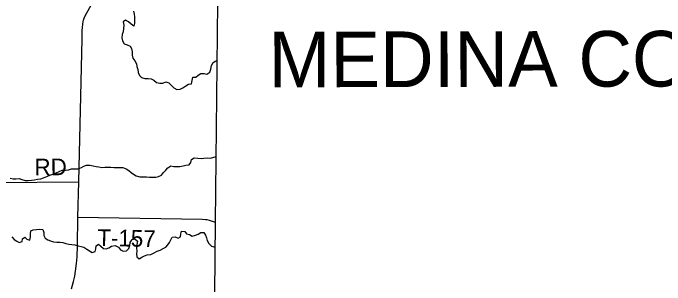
# Model space of a CAD drawing. Extents: x 1857828 to 2277390, y 930619 to 1324581.
# Drawn here: x 2082450 to 2094171, y 1160303 to 1165195 of the extents above; entities that cross this region are included whole.
import ezdxf

# ---------------------------------------------------------------- set-up
doc = ezdxf.new("R2010")
doc.units = 0
for name, color, linetype in [('GM_X_Adjacent_County', 7, 'Continuous'), ('GM_X_Adjacent_County_Text', 7, 'Continuous'), ('GM_X_County', 7, 'Continuous'), ('GM_X_County_Road', 7, 'Continuous'), ('GM_X_Minor_River', 7, 'Continuous'), ('GM_X_Township', 7, 'Continuous'), ('GM_X_Township_Road', 7, 'Continuous'), ('GM_X_Township_Road_Text', 7, 'Continuous')]:
    doc.layers.add(name, color=color, linetype=linetype)

msp = doc.modelspace()

# ---------------------------------------------------------------- linework, layer by layer
at = {"layer": 'GM_X_Adjacent_County'}
msp.add_lwpolyline([(2117908, 1193445), (2113523, 1193411), (2113466, 1188070), (2113428, 1184374), (2113417, 1179845), (2113408, 1176168), (2113399, 1174227), (2113372, 1168723), (2113358, 1166008), (2106159, 1165987), (2105360, 1165986), (2099554, 1165974), (2091388, 1165958), (2088816, 1165953), (2086130, 1165948), (2086087, 1161432), (2086019, 1154363)], dxfattribs=at)
at = {"layer": 'GM_X_County'}
msp.add_lwpolyline([(2117908, 1193445), (2113523, 1193411), (2113466, 1188070), (2113428, 1184374), (2113417, 1179845), (2113408, 1176168), (2113399, 1174227), (2113372, 1168723), (2113358, 1166008), (2106159, 1165987), (2105360, 1165986), (2099554, 1165974), (2091388, 1165958), (2088816, 1165953), (2086130, 1165948), (2086087, 1161432), (2086019, 1154363)], dxfattribs=at)
at = {"layer": 'GM_X_County_Road'}
msp.add_lwpolyline([(2083504, 1160231), (2083539, 1160367), (2083560, 1160459), (2083574, 1160552), (2083591, 1160692), (2083602, 1160810), (2083612, 1161005), (2083617, 1161525), (2083632, 1162159), (2083692, 1164734), (2083695, 1164883), (2083697, 1164933), (2083704, 1164997), (2083712, 1165043), (2083720, 1165069), (2083732, 1165101), (2083755, 1165155), (2083881, 1165379), (2084193, 1165926), (2084209, 1165955)], dxfattribs=at)
at = {"layer": 'GM_X_Minor_River'}
for points in [[(2084617, 1165229), (2084627, 1165177), (2084635, 1165125), (2084633, 1165068), (2084636, 1165010), (2084622, 1164962), (2084572, 1164996), (2084524, 1165039), (2084474, 1165065), (2084431, 1165037), (2084443, 1164975), (2084437, 1164925), (2084433, 1164858), (2084412, 1164808), (2084404, 1164750), (2084420, 1164694), (2084446, 1164643), (2084500, 1164623), (2084555, 1164601), (2084581, 1164556), (2084595, 1164500), (2084592, 1164440), (2084606, 1164382), (2084642, 1164333), (2084670, 1164283), (2084674, 1164231), (2084692, 1164182), (2084700, 1164128), (2084724, 1164072), (2084762, 1164035), (2084818, 1164017), (2084879, 1164019), (2084931, 1164014), (2084983, 1163986), (2085031, 1163948), (2085088, 1163931), (2085144, 1163931), (2085200, 1163959), (2085249, 1163939), (2085293, 1163898), (2085339, 1163848), (2085395, 1163822), (2085456, 1163827), (2085504, 1163849), (2085558, 1163885), (2085605, 1163913), (2085659, 1163923), (2085669, 1163983), (2085680, 1164043), (2085738, 1164043), (2085778, 1164079), (2085825, 1164107), (2085885, 1164109), (2085937, 1164098), (2085986, 1164132), (2086008, 1164184), (2086016, 1164251), (2086047, 1164305), (2086097, 1164337), (2086118, 1164321)], [(2085198, 1162370), (2085232, 1162408), (2085286, 1162445), (2085340, 1162433), (2085395, 1162433), (2085449, 1162437), (2085507, 1162446), (2085557, 1162458), (2085614, 1162464), (2085644, 1162506), (2085660, 1162561), (2085706, 1162589), (2085770, 1162587), (2085830, 1162577), (2085883, 1162586), (2085943, 1162588), (2086001, 1162586), (2086102, 1162612)], [(2082398, 1162224), (2082452, 1162214), (2082503, 1162214), (2082559, 1162216), (2082611, 1162198), (2082670, 1162182), (2082724, 1162181), (2082782, 1162187), (2082839, 1162195), (2082891, 1162205), (2082949, 1162211), (2082999, 1162230), (2083058, 1162256), (2083112, 1162278), (2083168, 1162297), (2083228, 1162323), (2083281, 1162345), (2083331, 1162368), (2083393, 1162370), (2083447, 1162374), (2083504, 1162390), (2083560, 1162394), (2083620, 1162393), (2083679, 1162417), (2083725, 1162443), (2083773, 1162457), (2083833, 1162456), (2083892, 1162444), (2083944, 1162436), (2083994, 1162426), (2084049, 1162416), (2084101, 1162420), (2084153, 1162421), (2084208, 1162421), (2084268, 1162417), (2084318, 1162417), (2084369, 1162419), (2084423, 1162414), (2084483, 1162394), (2084534, 1162364), (2084576, 1162326), (2084617, 1162294), (2084667, 1162264), (2084730, 1162248), (2084786, 1162246), (2084848, 1162246), (2084903, 1162241), (2084961, 1162243), (2085015, 1162245), (2085066, 1162253), (2085118, 1162279), (2085156, 1162326), (2085198, 1162370)], [(2082427, 1161167), (2082468, 1161123), (2082518, 1161093), (2082563, 1161069), (2082615, 1161084), (2082619, 1161134), (2082665, 1161166), (2082699, 1161128), (2082754, 1161108), (2082767, 1161168), (2082765, 1161221), (2082769, 1161277), (2082815, 1161297), (2082871, 1161301), (2082934, 1161308), (2082988, 1161302), (2083002, 1161248), (2083003, 1161195), (2083027, 1161143), (2083073, 1161117), (2083124, 1161097), (2083180, 1161082), (2083235, 1161076), (2083289, 1161076), (2083345, 1161068), (2083398, 1161052), (2083452, 1161038), (2083506, 1161030), (2083563, 1161025), (2083621, 1161009), (2083674, 1160997), (2083724, 1160981), (2083776, 1160949), (2083823, 1160915), (2083873, 1160885), (2083926, 1160903), (2083939, 1160954), (2083943, 1161010), (2083987, 1161036), (2084028, 1161002), (2084074, 1160962), (2084124, 1160954), (2084175, 1160971), (2084223, 1160999), (2084289, 1161013), (2084344, 1160981), (2084384, 1160933), (2084431, 1160911), (2084491, 1160915), (2084531, 1160958), (2084549, 1161012), (2084556, 1161068), (2084592, 1161119), (2084643, 1161131), (2084689, 1161093), (2084675, 1161033), (2084672, 1160970), (2084678, 1160912), (2084670, 1160862), (2084674, 1160812)], [(2084674, 1160812), (2084717, 1160774), (2084765, 1160802), (2084815, 1160826), (2084863, 1160846), (2084926, 1160853), (2084974, 1160875), (2085044, 1160911), (2085096, 1160930), (2085151, 1160958), (2085195, 1160984), (2085233, 1161023), (2085261, 1161069), (2085285, 1161113), (2085312, 1161163), (2085367, 1161172), (2085419, 1161146), (2085463, 1161170), (2085467, 1161224), (2085481, 1161272), (2085537, 1161267), (2085568, 1161225), (2085624, 1161209), (2085670, 1161179), (2085733, 1161199), (2085781, 1161219), (2085829, 1161250), (2085883, 1161250), (2085908, 1161202), (2085928, 1161154), (2085940, 1161103), (2085969, 1161049), (2086021, 1161003), (2086087, 1160986)]]:
    msp.add_lwpolyline(points, dxfattribs=at)
at = {"layer": 'GM_X_Township'}
msp.add_lwpolyline([(2059427, 1142930), (2059474, 1146652), (2059505, 1149211), (2059568, 1154416), (2059668, 1161839), (2059673, 1162156), (2059723, 1165822), (2062587, 1165821), (2067700, 1165827), (2072993, 1165838), (2079126, 1165869), (2084193, 1165926), (2086130, 1165948), (2086087, 1161432), (2086019, 1154363), (2086010, 1153403), (2085923, 1149181), (2085904, 1148231), (2085903, 1148166), (2085793, 1142829), (2081417, 1142846), (2072419, 1142880), (2061930, 1142920)], close=True, dxfattribs=at)
at = {"layer": 'GM_X_Township_Road'}
for points in [[(2080621, 1162134), (2083632, 1162159)], [(2083617, 1161525), (2085849, 1161486), (2085909, 1161484), (2085937, 1161479), (2085974, 1161471), (2086014, 1161459), (2086087, 1161432)]]:
    msp.add_lwpolyline(points, dxfattribs=at)

# ---------------------------------------------------------------- texts
at = {"layer": 'GM_X_Adjacent_County_Text'}
msp.add_text('MEDINA COUNTY', height=1000, rotation=0.1226, dxfattribs=at).set_placement((2087043, 1163859))
at = {"layer": 'GM_X_Township_Road_Text'}
for s, rotation, p in [('RD', 0.4936, (2082838, 1162274)), ('T-157', 358.8763, (2083964, 1161006))]:
    msp.add_text(s, height=300, rotation=rotation, dxfattribs=at).set_placement(p)

doc.saveas('drawing.dxf')
